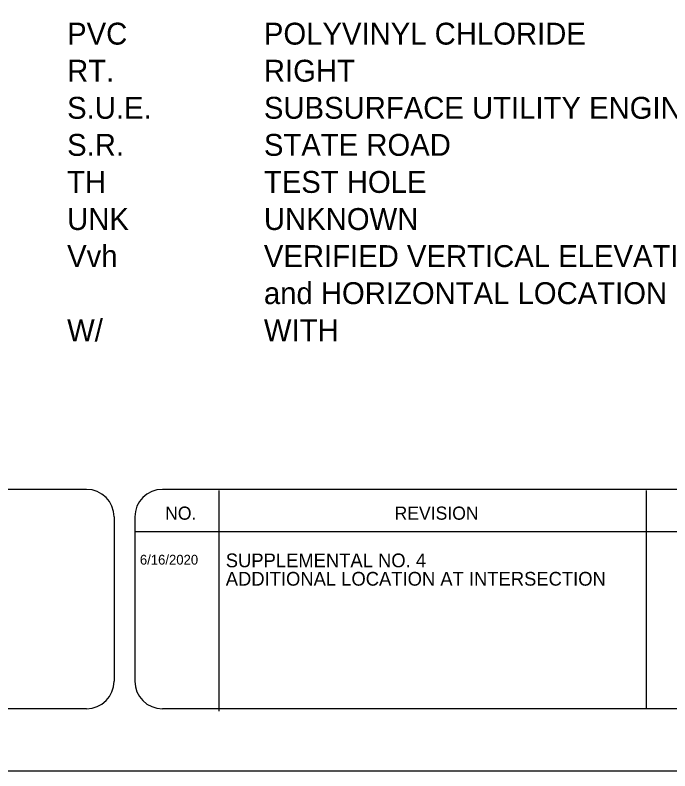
# Model space of a CAD drawing. Extents: x -769.4 to -731.2, y -2181.6 to -2171.
# Drawn here: x -762.643 to -760.548, y -2181.581 to -2179.165 of the extents above; entities that cross this region are included whole.
import ezdxf

# ---------------------------------------------------------------- set-up
doc = ezdxf.new("R2010")
doc.units = 0
for name, color, linetype in [('Default', 7, 'Continuous'), ('PlotBorder_dp', 7, 'Continuous'), ('TextSurveyLabel', 7, 'Continuous')]:
    doc.layers.add(name, color=color, linetype=linetype)

msp = doc.modelspace()

# ---------------------------------------------------------------- linework, layer by layer
at = {"layer": 'Default'}
for p, q in [((-762.4146, -2180.6815), (-762.8998, -2180.6815)), ((-760.1431, -2180.6815), (-762.172, -2180.6815)), ((-761.992, -2180.685), (-761.992, -2181.3908)), ((-760.6248, -2180.685), (-760.6248, -2181.3819)), ((-762.3264, -2180.7697), (-762.3264, -2181.2946)), ((-762.2603, -2180.7697), (-762.2603, -2181.2946)), ((-760.0513, -2180.8174), (-762.2567, -2180.8174)), ((-762.4146, -2181.3828), (-762.8998, -2181.3828)), ((-760.1431, -2181.3828), (-762.172, -2181.3828))]:
    msp.add_line(p, q, dxfattribs=at)
for centre, major_axis, start_param, end_param in [((-762.4146, -2180.7697), (0, 0.0882), 4.712389, 6.283185), ((-762.172, -2180.7697), (0, 0.0882), 0, 1.570796), ((-762.4146, -2181.2946), (0, 0.0882), 3.141593, 4.712389), ((-762.172, -2181.2946), (0, -0.0882), 4.712389, 6.283185)]:
    msp.add_ellipse(centre, major_axis=major_axis, ratio=0.999927, start_param=start_param, end_param=end_param, dxfattribs=at)
at = {"layer": 'PlotBorder_dp'}
msp.add_lwpolyline([(-769.2001, -2181.5815), (-752.7001, -2181.5815), (-752.7001, -2170.9815), (-769.2001, -2170.9815)], close=True, dxfattribs=at)

# ---------------------------------------------------------------- texts
at = {"layer": 'Default'}
for s, p in [('NO.', (-762.1633, -2180.7785)), ('REVISION', (-761.4293, -2180.7785))]:
    msp.add_text(s, height=0.04207, dxfattribs=at).set_placement(p)
at = {"layer": 'TextSurveyLabel'}
for s, p in [('PVC', (-762.4768, -2179.2594)), ('POLYVINYL CHLORIDE', (-761.8473, -2179.2594)), ('RT.', (-762.4768, -2179.3779)), ('RIGHT', (-761.8473, -2179.3779)), ('S.U.E.', (-762.4768, -2179.4965)), ('SUBSURFACE UTILITY ENGINEERING', (-761.8473, -2179.4965)), ('S.R.', (-762.4768, -2179.615)), ('STATE ROAD', (-761.8473, -2179.615)), ('TH', (-762.4768, -2179.7335)), ('TEST HOLE', (-761.8473, -2179.7335)), ('UNK', (-762.4768, -2179.8521)), ('UNKNOWN', (-761.8473, -2179.8521)), ('Vvh', (-762.4768, -2179.9706)), ('VERIFIED VERTICAL ELEVATION', (-761.8473, -2179.9706)), ('and HORIZONTAL LOCATION', (-761.8473, -2180.0891)), ('W/', (-762.4768, -2180.2077)), ('WITH', (-761.8473, -2180.2077))]:
    msp.add_text(s, height=0.07, rotation=360, dxfattribs=at).set_placement(p)
for s, height, p in [('6/16/2020', 0.03132, (-762.244, -2180.922)), ('SUPPLEMENTAL NO. 4', 0.04399, (-761.9693, -2180.9305)), ('ADDITIONAL LOCATION AT INTERSECTION ', 0.04399, (-761.9693, -2180.9893))]:
    msp.add_text(s, height=height, dxfattribs=at).set_placement(p)

doc.saveas('drawing.dxf')
